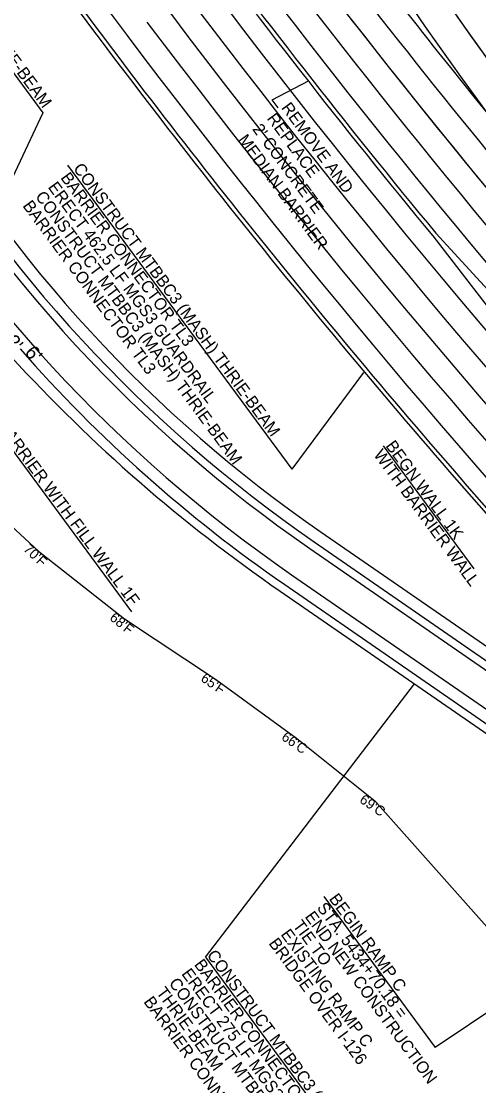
# Model space of a CAD drawing. Extents: x 1966090 to 1975830, y 788086 to 801233.
# Drawn here: x 1971145 to 1971374, y 795345 to 795878 of the extents above; entities that cross this region are included whole.
import ezdxf

# ---------------------------------------------------------------- set-up
doc = ezdxf.new("R2010")
doc.units = 0
for name, color, linetype in [('BR_PRESTRESSED BEAM', 7, 'Continuous'), ('BR_PROPOSED_DRAINAGE', 7, 'Continuous'), ('BR_REBAR', 7, 'Continuous'), ('RD_EX_Driveway_txCode', 7, 'Continuous'), ('RD_EX_RW_TX', 7, 'Continuous'), ('RD_EX_SU_Gas', 7, 'Continuous'), ('RD_PD_PaveShd', 7, 'Continuous'), ('RD_Sketch1', 7, 'Continuous'), ('RD_Sketch6', 7, 'Continuous'), ('RD_Sketch8', 7, 'Continuous')]:
    doc.layers.add(name, color=color, linetype=linetype)

msp = doc.modelspace()

# ---------------------------------------------------------------- linework, layer by layer
at = {"layer": 'BR_PRESTRESSED BEAM'}
for p, q in [((1971294.77, 795621.86), (1971389.49, 795556.41)), ((1971274.3, 795592.24), (1971411.8, 795497.23))]:
    msp.add_line(p, q, dxfattribs=at)
for centre, radius, start, end in [((1974296, 798203.94), 3890.72, 216.39766, 221.64292), ((1971687.01, 796189.52), 690, 209.92814, 235.35655), ((1971728.37, 796249.39), 798.76, 222.51368, 235.35655)]:
    msp.add_arc(centre, radius, start, end, dxfattribs=at)
at = {"layer": 'BR_PROPOSED_DRAINAGE'}
for p, q in [((1971112.87, 795649.59), (1971153.28, 795612.29)), ((1971153.28, 795612.29), (1971196.35, 795578.32)), ((1971196.35, 795578.32), (1971242, 795548.18)), ((1971242, 795548.18), (1971282.55, 795518.67)), ((1971282.55, 795518.67), (1971321.63, 795487.28)), ((1971392.31, 795407.67), (1971321.63, 795487.28))]:
    msp.add_line(p, q, dxfattribs=at)
at = {"layer": 'BR_REBAR'}
for radius in [1805, 1803]:
    msp.add_arc((1972855.69, 796921.19), radius, 211.88652, 221.68841, dxfattribs=at)
at = {"layer": 'RD_EX_SU_Gas'}
for radius, start, end in [(3784.72, 216.39766, 226.1479), (3784.72, 216.39766, 236.97136), (3796.72, 216.39766, 236.97136), (3842.72, 216.39766, 244.09898), (3854.72, 216.39766, 243.9112), (3866.72, 216.9932, 243.9112)]:
    msp.add_arc((1974296, 798203.94), radius, start, end, dxfattribs=at)
at = {"layer": 'RD_PD_PaveShd'}
for p, q in [((1971350.67, 795770.24), (1971390.42, 795718.68)), ((1971352.19, 795771.54), (1971396.11, 795723.57)), ((1971291.36, 795616.92), (1971386.08, 795551.47)), ((1971276.58, 795595.53), (1971414.07, 795500.52))]:
    msp.add_line(p, q, dxfattribs=at)
for centre, radius, start, end in [((1972855.69, 796921.19), 1805, 211.88652, 221.68841), ((1974296, 798203.94), 3818.72, 216.39766, 219.56614), ((1974296, 798203.94), 3820.72, 216.39766, 219.56665), ((1974296, 798203.94), 3888.72, 216.39766, 221.6415), ((1971687.01, 796189.52), 696, 209.92814, 235.35655), ((1971687.01, 796189.52), 722, 221.24065, 235.35655)]:
    msp.add_arc(centre, radius, start, end, dxfattribs=at)
at = {"layer": 'RD_Sketch1'}
msp.add_arc((1972855.69, 796921.19), 1820, 209.01045, 218.45481, dxfattribs=at)
at = {"layer": 'RD_Sketch6'}
for p, q in [((1971055.16, 795967.79), (1971155.48, 795831.71)), ((1971270.31, 795838.3), (1971288.83, 795847.92)), ((1971273.25, 795834.32), (1971270.31, 795838.3)), ((1971155.48, 795831.71), (1971131.32, 795780.49)), ((1971167.9, 795805.52), (1971280.13, 795653.28)), ((1971315.95, 795701.77), (1971280.13, 795653.28)), ((1971119.19, 795691.4), (1971199.91, 795581.9)), ((1971325.81, 795665.02), (1971371.2, 795603.45)), ((1971236.92, 795408.9), (1971341.5, 795545.8)), ((1971296.1, 795439.34), (1971351.85, 795363.71)), ((1971449.73, 795429.54), (1971351.85, 795363.71)), ((1971236.92, 795408.9), (1971331.98, 795279.95))]:
    msp.add_line(p, q, dxfattribs=at)
at = {"layer": 'RD_Sketch8'}
for p, q in [((1971289.08, 795613.63), (1971489.67, 795475.03)), ((1971279.99, 795600.47), (1971480.58, 795461.86))]:
    msp.add_line(p, q, dxfattribs=at)
for centre, radius, start, end in [((1972855.69, 796921.19), 1820, 205.76109, 221.68841), ((1972855.69, 796921.19), 1836, 205.76109, 216.40394), ((1974296, 798203.94), 3760.72, 216.39766, 218.51982), ((1974296, 798203.94), 3772.72, 216.39766, 219.89735), ((1974296, 798203.94), 3808.72, 216.39766, 236.97136), ((1974296, 798203.94), 3830.72, 216.39766, 243.9112), ((1974296, 798203.94), 3878.72, 216.39766, 241.30888), ((1974296, 798203.94), 3760.72, 218.51982, 223.11151), ((1971687.01, 796189.52), 700, 209.92814, 235.35655), ((1971687.01, 796189.52), 716, 209.92814, 235.35655)]:
    msp.add_arc(centre, radius, start, end, dxfattribs=at)

# ---------------------------------------------------------------- texts
at = {"layer": 'RD_EX_Driveway_txCode'}
for s, rotation, p in [("12'", 309.4293, (1971133.02, 795721.14)), ("6'", 310.1999, (1971146.01, 795711.56))]:
    msp.add_text(s, height=7, rotation=rotation, dxfattribs=at).set_placement(p)
at = {"layer": 'RD_EX_RW_TX'}
for s, rotation, p in [("70'F", 317.2423, (1971145.38, 795612.78)), ("68'F", 321.2434, (1971188.52, 795578.2)), ("65'F", 325.2445, (1971234.12, 795547.57)), ("66'C", 325.3566, (1971274.52, 795518.14)), ("69'C", 325.3566, (1971313.6, 795486.76))]:
    msp.add_text(s, height=5, rotation=rotation, dxfattribs=at).set_placement(p)
at = {"layer": 'RD_Sketch6'}
for s, height, rotation, p in [('CONSTRUCT MTBBC3 (MASH) THRIE-BEAM', 5.9996, 306.4243, (1971056.11, 795968.49)), ('REMOVE AND', 6, 306.4243, (1971274.6, 795834.27)), ('REPLACE', 6, 306.4243, (1971267.36, 795828.93)), ("2' CONCRETE", 5.9996, 306.4243, (1971260.12, 795823.58)), ('MEDIAN BARRIER', 5.9996, 306.4243, (1971252.88, 795818.24)), ('CONSTRUCT MTBBC3 (MASH) THRIE-BEAM', 5.9996, 306.4243, (1971170.44, 795803.88)), ('BARRIER CONNECTOR TL3', 5.9996, 306.4243, (1971164.11, 795799.21)), ('ERECT 462.5 LF MGS3 GUARDRAIL', 5.9996, 306.4243, (1971157.78, 795794.54)), ('BARRIER CONNECTOR TL3', 5.9996, 306.4243, (1971145.12, 795785.2)), ('CONSTRUCT MTBBC3 (MASH) THRIE-BEAM', 5.9996, 306.4243, (1971151.45, 795789.87)), ('END BARRIER WITH FILL WALL 1F', 5.9996, 306.5574, (1971121.29, 795689.92)), ('BEGN WALL 1K', 5.9996, 306.3977, (1971326.8, 795664.96)), ('WITH BARRIER WALL', 5.9996, 306.3977, (1971320.77, 795660.51)), ('STA. 5434+70.18 = ', 5.9996, 306.3977, (1971292.44, 795433.63)), ('BEGIN RAMP C ', 5.9996, 306.3977, (1971298.48, 795438.08)), ('END NEW CONSTRUCTION', 5.9996, 306.3977, (1971286.4, 795429.18)), ('TIE TO ', 6, 306.3977, (1971280.37, 795424.73)), ('EXISTING RAMP C', 5.9996, 306.3977, (1971274.33, 795420.28)), ('BRIDGE OVER I-126', 5.9996, 306.3977, (1971268.29, 795415.83)), ('CONSTRUCT MTBBC3 (MASH) THRIE-BEAM', 5.9996, 306.4243, (1971237.31, 795409.88)), ('BARRIER CONNECTOR TL3', 5.9996, 306.4243, (1971230.98, 795405.21)), ('ERECT 275 LF MGS3 GUARDRAIL', 5.9996, 306.4243, (1971224.65, 795400.54)), ('THRIE-BEAM', 6, 306.4243, (1971211.99, 795391.2)), ('CONSTRUCT MTBBC3 (MASH)', 5.9996, 306.4243, (1971218.32, 795395.87)), ('BARRIER CONNECTOR TL3', 5.9996, 306.4243, (1971205.67, 795386.53))]:
    msp.add_text(s, height=height, rotation=rotation, dxfattribs=at).set_placement(p)

doc.saveas('drawing.dxf')
